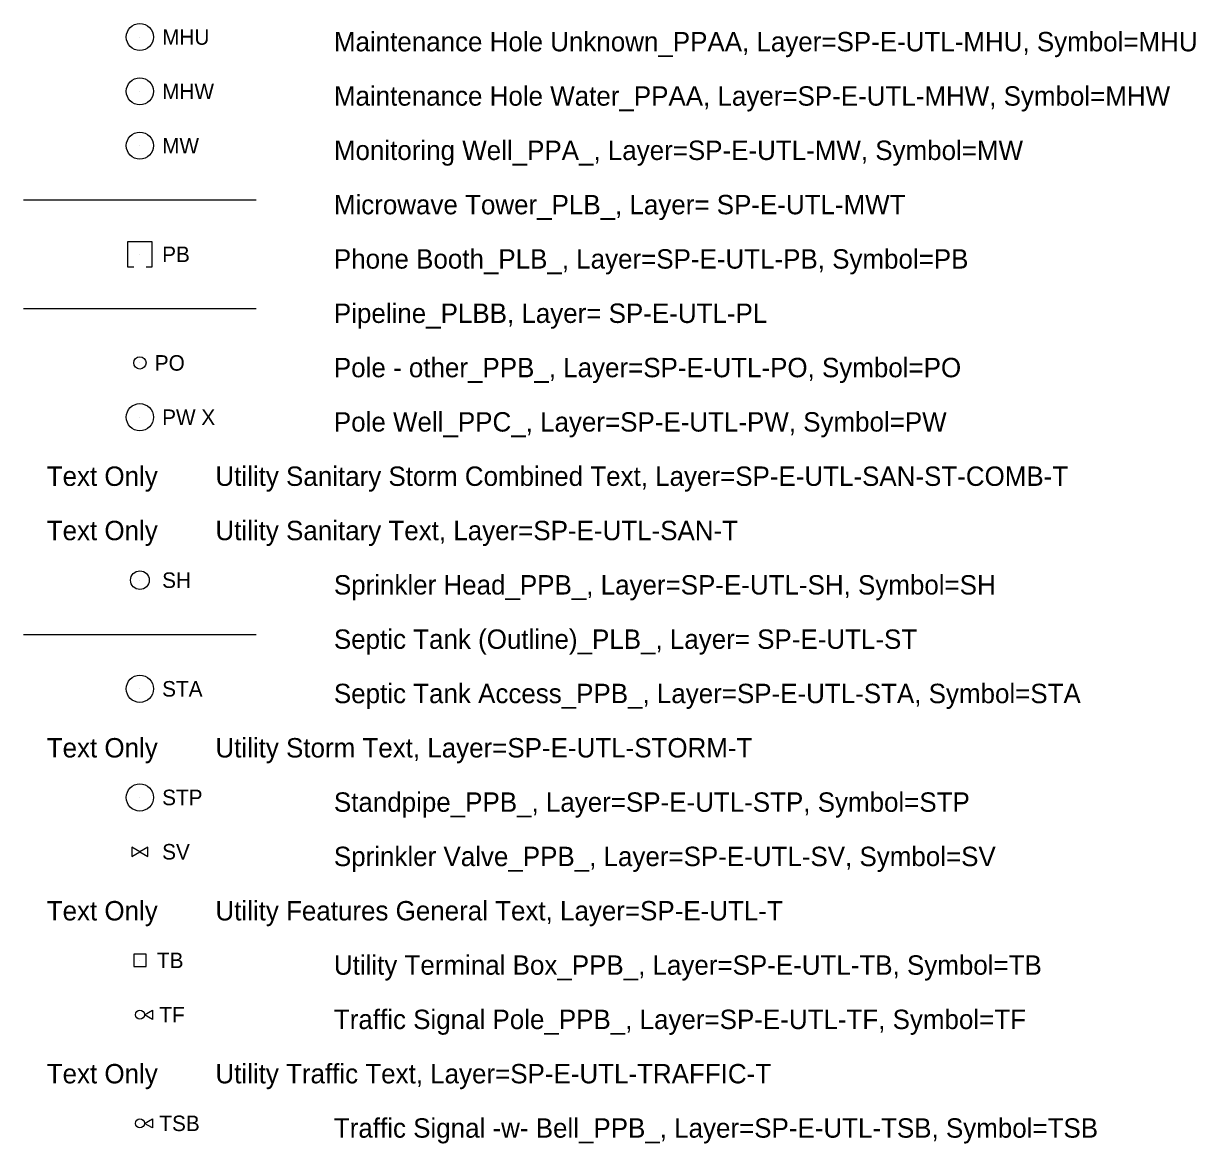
# Model space of a CAD drawing. Extents: x 500528 to 502626, y 4210261 to 4212624.
# Drawn here: x 501386.5 to 501537.6, y 4210853 to 4210997.3 of the extents above; entities that cross this region are included whole.
import ezdxf

# ---------------------------------------------------------------- set-up
doc = ezdxf.new("R2010")
doc.units = 0
for name, color, linetype in [('SP-E-UTL-COMB-T', 7, 'Continuous'), ('SP-E-UTL-MHU', 7, 'Continuous'), ('SP-E-UTL-MHW', 7, 'Continuous'), ('SP-E-UTL-MW', 7, 'Continuous'), ('SP-E-UTL-MWT', 7, 'Continuous'), ('SP-E-UTL-PB', 7, 'Continuous'), ('SP-E-UTL-PL', 7, 'Continuous'), ('SP-E-UTL-PO', 7, 'Continuous'), ('SP-E-UTL-PW', 7, 'Continuous'), ('SP-E-UTL-SAN-ST-COMB-T', 7, 'Continuous'), ('SP-E-UTL-SAN-T', 7, 'Continuous'), ('SP-E-UTL-SH', 7, 'Continuous'), ('SP-E-UTL-ST', 7, 'Continuous'), ('SP-E-UTL-STA', 7, 'Continuous'), ('SP-E-UTL-STORM-T', 7, 'Continuous'), ('SP-E-UTL-STP', 7, 'Continuous'), ('SP-E-UTL-SV', 7, 'Continuous'), ('SP-E-UTL-T', 7, 'Continuous'), ('SP-E-UTL-TB', 7, 'Continuous'), ('SP-E-UTL-TF', 7, 'Continuous'), ('SP-E-UTL-TRAFFIC-T', 7, 'Continuous'), ('SP-E-UTL-TSB', 7, 'Continuous'), ('SP-E-UTL-WATER-T', 7, 'Continuous')]:
    doc.layers.add(name, color=color, linetype=linetype)

# ---------------------------------------------------------------- blocks, each defined once
blk = doc.blocks.new('MHU')
at = {"layer": 'SP-E-UTL-MHU'}
blk.add_lwpolyline([(0, 0), (0, 0)], dxfattribs=at)
blk.add_circle((0, 0), 0.175, dxfattribs=at)
at = {"layer": 'SP-E-UTL-T'}
blk.add_text('MHU', height=0.2, dxfattribs=at).set_placement((0.287, -0.1))
blk = doc.blocks.new('MHW')
at = {"layer": 'SP-E-UTL-MHW'}
blk.add_lwpolyline([(0, 0), (0, 0)], dxfattribs=at)
blk.add_circle((0, 0), 0.175, dxfattribs=at)
at = {"layer": 'SP-E-UTL-WATER-T'}
blk.add_text('MHW', height=0.2, dxfattribs=at).set_placement((0.287, -0.1))
blk = doc.blocks.new('MW')
at = {"layer": 'SP-E-UTL-MW'}
blk.add_lwpolyline([(0, 0), (0, 0)], dxfattribs=at)
blk.add_circle((0, 0), 0.175, dxfattribs=at)
at = {"layer": 'SP-E-UTL-T'}
blk.add_text('MW', height=0.2, dxfattribs=at).set_placement((0.287, -0.1))
blk = doc.blocks.new('PB')
at = {"layer": 'SP-E-UTL-PB'}
for points in [[(0.08, -0.16), (0.16, -0.16), (0.16, 0.16), (-0.16, 0.16), (-0.16, -0.16), (-0.08, -0.16)], [(0, 0), (0, 0)]]:
    blk.add_lwpolyline(points, dxfattribs=at)
at = {"layer": 'SP-E-UTL-T'}
blk.add_text('PB', height=0.2, dxfattribs=at).set_placement((0.287, -0.1))
blk = doc.blocks.new('PO')
at = {"layer": 'SP-E-UTL-PO'}
blk.add_lwpolyline([(0, 0), (0, 0)], dxfattribs=at)
blk.add_circle((0, 0), 0.08, dxfattribs=at)
at = {"layer": 'SP-E-UTL-T'}
blk.add_text('PO', height=0.2, dxfattribs=at).set_placement((0.192, -0.1))
blk = doc.blocks.new('PW')
at = {"layer": 'SP-E-UTL-PW'}
blk.add_lwpolyline([(0, 0), (0, 0)], dxfattribs=at)
blk.add_circle((0, 0), 0.175, dxfattribs=at)
at = {"layer": 'SP-E-UTL-T'}
blk.add_text('PW X', height=0.2, dxfattribs=at).set_placement((0.287, -0.1))
blk = doc.blocks.new('SH')
at = {"layer": 'SP-E-UTL-SH'}
blk.add_lwpolyline([(0, 0), (0, 0)], dxfattribs=at)
blk.add_circle((0, 0), 0.12, dxfattribs=at)
at = {"layer": 'SP-E-UTL-T'}
blk.add_text('SH', height=0.2, dxfattribs=at).set_placement((0.287, -0.1))
blk = doc.blocks.new('STA')
at = {"layer": 'SP-E-UTL-STA'}
blk.add_lwpolyline([(0, 0), (0, 0)], dxfattribs=at)
blk.add_circle((0, 0), 0.175, dxfattribs=at)
at = {"layer": 'SP-E-UTL-T'}
blk.add_text('STA', height=0.2, dxfattribs=at).set_placement((0.287, -0.1))
blk = doc.blocks.new('STP')
at = {"layer": 'SP-E-UTL-STP'}
blk.add_lwpolyline([(0, 0), (0, 0)], dxfattribs=at)
blk.add_circle((0, 0), 0.175, dxfattribs=at)
at = {"layer": 'SP-E-UTL-T'}
blk.add_text('STP', height=0.2, dxfattribs=at).set_placement((0.287, -0.1))
blk = doc.blocks.new('SV')
at = {"layer": 'SP-E-UTL-SV'}
for points in [[(-0.104, -0.06), (0, 0), (-0.104, 0.06), (-0.104, -0.06)], [(0.104, -0.06), (0.104, 0.06), (0, 0), (0.104, -0.06)]]:
    blk.add_lwpolyline(points, dxfattribs=at)
at = {"layer": 'SP-E-UTL-T'}
blk.add_text('SV', height=0.2, dxfattribs=at).set_placement((0.287, -0.1))
blk = doc.blocks.new('TB')
at = {"layer": 'SP-E-UTL-TB'}
for points in [[(-0.08, 0.08), (-0.08, -0.08), (0.08, -0.08), (0.08, 0.08), (-0.08, 0.08)], [(0, 0), (0, 0)]]:
    blk.add_lwpolyline(points, dxfattribs=at)
at = {"layer": 'SP-E-UTL-T'}
blk.add_text('TB', height=0.2, dxfattribs=at).set_placement((0.22, -0.1))
blk = doc.blocks.new('TF')
at = {"layer": 'SP-E-UTL-TF'}
for points in [[(0, 0), (0, 0)], [(0.058, 0), (0.162, 0.06), (0.162, -0.06), (0.058, 0)]]:
    blk.add_lwpolyline(points, dxfattribs=at)
blk.add_circle((0, 0), 0.0585, dxfattribs=at)
at = {"layer": 'SP-E-UTL-TRAFFIC-T'}
blk.add_text('TF', height=0.2, dxfattribs=at).set_placement((0.251, -0.1))
blk = doc.blocks.new('TSB')
at = {"layer": 'SP-E-UTL-TSB'}
for points in [[(0, 0), (0, 0)], [(0.058, 0), (0.162, 0.06), (0.162, -0.06), (0.058, 0)]]:
    blk.add_lwpolyline(points, dxfattribs=at)
blk.add_circle((0, 0), 0.0585, dxfattribs=at)
at = {"layer": 'SP-E-UTL-COMB-T'}
blk.add_text('TSB', height=0.2, dxfattribs=at).set_placement((0.251, -0.1))

msp = doc.modelspace()

# ---------------------------------------------------------------- linework, layer by layer
at = {"layer": 'SP-E-UTL-MWT'}
msp.add_line((501386.55, 4210974.59), (501416.55, 4210974.59), dxfattribs=at)
at = {"layer": 'SP-E-UTL-PL'}
msp.add_line((501386.55, 4210960.59), (501416.55, 4210960.59), dxfattribs=at)
at = {"layer": 'SP-E-UTL-ST'}
msp.add_line((501386.55, 4210918.59), (501416.55, 4210918.59), dxfattribs=at)

# ---------------------------------------------------------------- block references
at = {"layer": 'SP-E-UTL-MHU', "xscale": 10, "yscale": 10}
msp.add_blockref('MHU', (501401.55, 4210995.59), dxfattribs=at)
at = {"layer": 'SP-E-UTL-MHW', "xscale": 10, "yscale": 10}
msp.add_blockref('MHW', (501401.55, 4210988.59), dxfattribs=at)
at = {"layer": 'SP-E-UTL-MW', "xscale": 10, "yscale": 10}
msp.add_blockref('MW', (501401.55, 4210981.59), dxfattribs=at)
at = {"layer": 'SP-E-UTL-PB', "xscale": 10, "yscale": 10}
msp.add_blockref('PB', (501401.55, 4210967.59), dxfattribs=at)
at = {"layer": 'SP-E-UTL-PO', "xscale": 10, "yscale": 10}
msp.add_blockref('PO', (501401.55, 4210953.59), dxfattribs=at)
at = {"layer": 'SP-E-UTL-PW', "xscale": 10, "yscale": 10}
msp.add_blockref('PW', (501401.55, 4210946.59), dxfattribs=at)
at = {"layer": 'SP-E-UTL-SH', "xscale": 10, "yscale": 10}
msp.add_blockref('SH', (501401.55, 4210925.59), dxfattribs=at)
at = {"layer": 'SP-E-UTL-STA', "xscale": 10, "yscale": 10}
msp.add_blockref('STA', (501401.55, 4210911.59), dxfattribs=at)
at = {"layer": 'SP-E-UTL-STP', "xscale": 10, "yscale": 10}
msp.add_blockref('STP', (501401.55, 4210897.59), dxfattribs=at)
at = {"layer": 'SP-E-UTL-SV', "xscale": 10, "yscale": 10}
msp.add_blockref('SV', (501401.55, 4210890.59), dxfattribs=at)
at = {"layer": 'SP-E-UTL-TB', "xscale": 10, "yscale": 10}
msp.add_blockref('TB', (501401.55, 4210876.59), dxfattribs=at)
at = {"layer": 'SP-E-UTL-TF', "xscale": 10, "yscale": 10}
msp.add_blockref('TF', (501401.55, 4210869.59), dxfattribs=at)
at = {"layer": 'SP-E-UTL-TSB', "xscale": 10, "yscale": 10}
msp.add_blockref('TSB', (501401.55, 4210855.59), dxfattribs=at)

# ---------------------------------------------------------------- texts
at = {"layer": 'SP-E-UTL-MHU'}
msp.add_text('Maintenance Hole Unknown_PPAA, Layer=SP-E-UTL-MHU, Symbol=MHU ', height=2.5, dxfattribs=at).set_placement((501426.55, 4210993.74))
at = {"layer": 'SP-E-UTL-MHW'}
msp.add_text('Maintenance Hole Water_PPAA, Layer=SP-E-UTL-MHW, Symbol=MHW ', height=2.5, dxfattribs=at).set_placement((501426.55, 4210986.74))
at = {"layer": 'SP-E-UTL-MW'}
msp.add_text('Monitoring Well_PPA_, Layer=SP-E-UTL-MW, Symbol=MW ', height=2.5, dxfattribs=at).set_placement((501426.55, 4210979.74))
at = {"layer": 'SP-E-UTL-MWT'}
msp.add_text('Microwave Tower_PLB_, Layer= SP-E-UTL-MWT ', height=2.5, dxfattribs=at).set_placement((501426.55, 4210972.74))
at = {"layer": 'SP-E-UTL-PB'}
msp.add_text('Phone Booth_PLB_, Layer=SP-E-UTL-PB, Symbol=PB ', height=2.5, dxfattribs=at).set_placement((501426.55, 4210965.74))
at = {"layer": 'SP-E-UTL-PL'}
msp.add_text('Pipeline_PLBB, Layer= SP-E-UTL-PL ', height=2.5, dxfattribs=at).set_placement((501426.55, 4210958.74))
at = {"layer": 'SP-E-UTL-PO'}
msp.add_text('Pole - other_PPB_, Layer=SP-E-UTL-PO, Symbol=PO ', height=2.5, dxfattribs=at).set_placement((501426.55, 4210951.74))
at = {"layer": 'SP-E-UTL-PW'}
msp.add_text('Pole Well_PPC_, Layer=SP-E-UTL-PW, Symbol=PW ', height=2.5, dxfattribs=at).set_placement((501426.55, 4210944.74))
at = {"layer": 'SP-E-UTL-SAN-ST-COMB-T'}
msp.add_text('Text Only        Utility Sanitary Storm Combined Text, Layer=SP-E-UTL-SAN-ST-COMB-T', height=2.5, dxfattribs=at).set_placement((501389.55, 4210937.74))
at = {"layer": 'SP-E-UTL-SAN-T'}
msp.add_text('Text Only        Utility Sanitary Text, Layer=SP-E-UTL-SAN-T', height=2.5, dxfattribs=at).set_placement((501389.55, 4210930.74))
at = {"layer": 'SP-E-UTL-SH'}
msp.add_text('Sprinkler Head_PPB_, Layer=SP-E-UTL-SH, Symbol=SH ', height=2.5, dxfattribs=at).set_placement((501426.55, 4210923.74))
at = {"layer": 'SP-E-UTL-ST'}
msp.add_text('Septic Tank (Outline)_PLB_, Layer= SP-E-UTL-ST ', height=2.5, dxfattribs=at).set_placement((501426.55, 4210916.74))
at = {"layer": 'SP-E-UTL-STA'}
msp.add_text('Septic Tank Access_PPB_, Layer=SP-E-UTL-STA, Symbol=STA ', height=2.5, dxfattribs=at).set_placement((501426.55, 4210909.74))
at = {"layer": 'SP-E-UTL-STORM-T'}
msp.add_text('Text Only        Utility Storm Text, Layer=SP-E-UTL-STORM-T', height=2.5, dxfattribs=at).set_placement((501389.55, 4210902.74))
at = {"layer": 'SP-E-UTL-STP'}
msp.add_text('Standpipe_PPB_, Layer=SP-E-UTL-STP, Symbol=STP ', height=2.5, dxfattribs=at).set_placement((501426.55, 4210895.74))
at = {"layer": 'SP-E-UTL-SV'}
msp.add_text('Sprinkler Valve_PPB_, Layer=SP-E-UTL-SV, Symbol=SV ', height=2.5, dxfattribs=at).set_placement((501426.55, 4210888.74))
at = {"layer": 'SP-E-UTL-T'}
msp.add_text('Text Only        Utility Features General Text, Layer=SP-E-UTL-T', height=2.5, dxfattribs=at).set_placement((501389.55, 4210881.74))
at = {"layer": 'SP-E-UTL-TB'}
msp.add_text('Utility Terminal Box_PPB_, Layer=SP-E-UTL-TB, Symbol=TB ', height=2.5, dxfattribs=at).set_placement((501426.55, 4210874.74))
at = {"layer": 'SP-E-UTL-TF'}
msp.add_text('Traffic Signal Pole_PPB_, Layer=SP-E-UTL-TF, Symbol=TF ', height=2.5, dxfattribs=at).set_placement((501426.55, 4210867.74))
at = {"layer": 'SP-E-UTL-TRAFFIC-T'}
msp.add_text('Text Only        Utility Traffic Text, Layer=SP-E-UTL-TRAFFIC-T', height=2.5, dxfattribs=at).set_placement((501389.55, 4210860.74))
at = {"layer": 'SP-E-UTL-TSB'}
msp.add_text('Traffic Signal -w- Bell_PPB_, Layer=SP-E-UTL-TSB, Symbol=TSB ', height=2.5, dxfattribs=at).set_placement((501426.55, 4210853.74))

doc.saveas('drawing.dxf')
